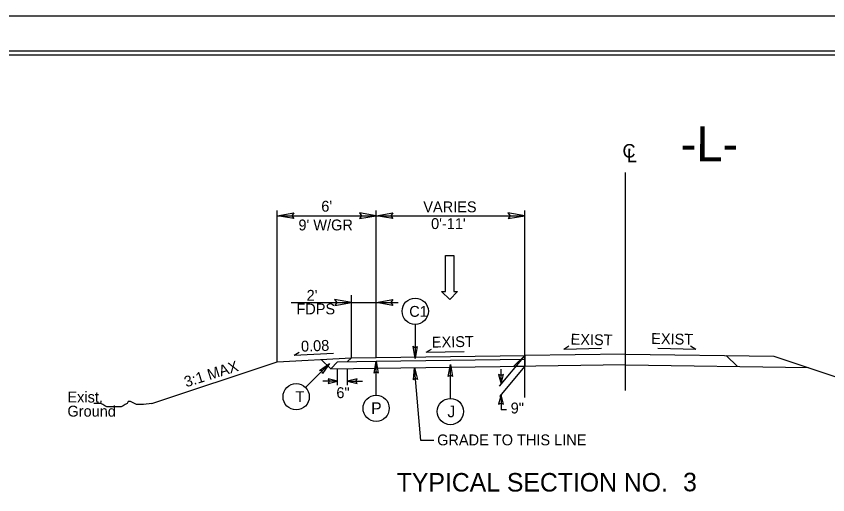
# Model space of a CAD drawing. Extents: x 1497225 to 1499181, y 579958 to 582278.
# Drawn here: x 1497748 to 1498271, y 580750 to 581058 of the extents above; entities that cross this region are included whole.
import ezdxf

# ---------------------------------------------------------------- set-up
doc = ezdxf.new("R2010")
doc.units = 0
for name, color, linetype in [('Old_Level_1', 7, 'Continuous'), ('Old_Level_11', 7, 'Continuous'), ('Old_Level_4', 7, 'Continuous'), ('Sheet Cutting Line CELL', 7, 'Continuous'), ('Sheet Plot Border Inside CELL', 7, 'Continuous'), ('Sheet Plot Border Outside CELL', 7, 'Continuous'), ('Sheet Typical CELL', 7, 'Continuous'), ('Typical ID Circle CELL', 7, 'Continuous'), ('Typical Terminator CELL', 7, 'Continuous'), ('Typical Text ID Circle CELL', 7, 'Continuous'), ('Typical Text Label CELL', 7, 'Continuous')]:
    doc.layers.add(name, color=color, linetype=linetype)

# ---------------------------------------------------------------- blocks, each defined once
blk = doc.blocks.new('TERMINATOR')
at = {"layer": 'Typical Terminator CELL'}
blk.add_lwpolyline([(-0.469, 0.081), (0, 0), (-0.471, -0.083), (-0.411, 0)], close=True, dxfattribs=at)

msp = doc.modelspace()

# ---------------------------------------------------------------- linework, layer by layer
at = {"layer": 'Old_Level_1'}
for p, q in [((1498140.92, 580816.81), (1498140.92, 580957.33)), ((1497916.36, 580835.27), (1497916.36, 580932.92)), ((1497916.36, 580929.48), (1497980.21, 580929.48)), ((1497980.21, 580838.15), (1497980.21, 580932.92)), ((1497980.21, 580929.48), (1498075.97, 580929.48)), ((1498075.97, 580812.23), (1498075.97, 580932.92)), ((1497964.25, 580837.93), (1497964.25, 580878.15)), ((1497925.39, 580873.5), (1497994.41, 580873.5)), ((1497964.25, 580873.5), (1497980.21, 580873.5)), ((1498101.09, 580843.51), (1498104.47, 580845.55)), ((1498186.23, 580843.32), (1498182.86, 580845.36)), ((1497927.3, 580839.48), (1497930.67, 580841.52)), ((1497927.3, 580839.48), (1497952.81, 580840.85)), ((1497980.21, 580838.15), (1498075.97, 580839.42)), ((1498012.55, 580841.42), (1498015.92, 580843.46)), ((1498012.55, 580841.42), (1498037.01, 580841.91)), ((1498075.97, 580839.42), (1498059.49, 580819.59)), ((1498075.97, 580839.42), (1498068.81, 580832.26)), ((1498140.92, 580840.3), (1498075.97, 580839.42)), ((1498075.97, 580839.42), (1498075.97, 580832.5)), ((1498101.09, 580843.51), (1498125.56, 580844)), ((1498140.92, 580840.3), (1498236.52, 580839.01)), ((1498186.23, 580843.32), (1498161.77, 580843.81)), ((1498205.87, 580839.42), (1498213.04, 580832.26)), ((1498236.52, 580839.01), (1498329.02, 580808.17)), ((1497835.57, 580808.34), (1497916.36, 580835.27)), ((1497916.36, 580835.27), (1497964.25, 580837.93)), ((1497944.89, 580836.85), (1497950.92, 580830.83)), ((1497950.92, 580830.83), (1497955.41, 580835.32)), ((1497955.41, 580835.32), (1497980.21, 580835.66)), ((1497961.73, 580835.41), (1497964.25, 580837.93)), ((1497964.25, 580837.93), (1497980.21, 580838.15)), ((1497980.21, 580835.66), (1498075.97, 580836.94)), ((1497950.92, 580830.83), (1497980.21, 580831.23)), ((1497955.41, 580820.22), (1497955.41, 580830.89)), ((1497961.73, 580820.22), (1497961.73, 580830.98)), ((1497980.21, 580831.23), (1498075.97, 580832.5)), ((1498008.96, 580784.68), (1498004.86, 580831.56)), ((1498075.97, 580832.5), (1498059.64, 580812.86)), ((1498060.69, 580821.04), (1498060.69, 580830.67)), ((1498140.92, 580833.44), (1498068.81, 580832.39)), ((1498140.92, 580833.31), (1498258.77, 580831.59)), ((1497955.41, 580822.79), (1497945.79, 580822.79)), ((1497961.73, 580822.79), (1497971.36, 580822.79)), ((1498060.69, 580814.13), (1498060.69, 580804.46)), ((1498064.24, 580804.46), (1498060.69, 580804.46)), ((1498017.35, 580784.68), (1498008.96, 580784.68))]:
    msp.add_line(p, q, dxfattribs=at)
msp.add_lwpolyline([(1497835.57, 580808.34), (1497830.33, 580807.69), (1497829.02, 580807.69), (1497827.05, 580807.69), (1497825.74, 580807.69), (1497824.42, 580808.34), (1497823.11, 580809), (1497821.8, 580809.66), (1497820.49, 580809.66), (1497819.83, 580808.34), (1497818.52, 580807.69), (1497817.21, 580807.03), (1497815.9, 580806.38), (1497814.59, 580806.38), (1497813.28, 580806.38), (1497811.97, 580806.38), (1497810.65, 580806.38), (1497809.34, 580806.38), (1497808.03, 580806.38), (1497806.72, 580806.38), (1497805.41, 580807.03), (1497804.1, 580807.69), (1497802.79, 580808.34), (1497800.82, 580808.34), (1497799.51, 580808.34), (1497798.2, 580808.34)], dxfattribs=at)
at = {"layer": 'Old_Level_11'}
for points in [[(1497927.08, 580927.6), (1497916.36, 580929.48), (1497927.17, 580931.37), (1497925.79, 580929.48)], [(1497969.48, 580927.6), (1497980.21, 580929.48), (1497969.4, 580931.37), (1497970.77, 580929.48)], [(1497990.93, 580927.6), (1497980.21, 580929.48), (1497991.02, 580931.37), (1497989.64, 580929.48)], [(1498065.24, 580927.6), (1498075.97, 580929.48), (1498065.16, 580931.37), (1498066.53, 580929.48)], [(1497953.52, 580871.61), (1497964.25, 580873.5), (1497953.44, 580875.38), (1497954.81, 580873.5)], [(1497990.93, 580871.61), (1497980.21, 580873.5), (1497991.02, 580875.38), (1497989.64, 580873.5)]]:
    msp.add_lwpolyline(points, close=True, dxfattribs=at)
at = {"layer": 'Old_Level_4'}
for p, q in [((1498024.83, 580880.65), (1498024.83, 580903.75)), ((1498024.83, 580903.75), (1498030.28, 580903.75)), ((1498030.28, 580903.75), (1498030.28, 580880.65)), ((1498027.64, 580875.45), (1498022.36, 580880.65)), ((1498022.36, 580880.65), (1498024.83, 580880.65)), ((1498032.75, 580880.65), (1498027.64, 580875.45)), ((1498030.28, 580880.65), (1498032.75, 580880.65))]:
    msp.add_line(p, q, dxfattribs=at)
msp.add_lwpolyline([(1498004.21, 580823.74), (1498004.86, 580831.56), (1498006.91, 580823.93), (1498005.45, 580824.79)], close=True, dxfattribs=at)
at = {"layer": 'Sheet Cutting Line CELL'}
msp.add_line((1498909.23, 581058.02), (1497225.23, 581058.02), dxfattribs=at)
at = {"layer": 'Sheet Plot Border Inside CELL'}
msp.add_lwpolyline([(1498904.73, 581035.57), (1497238.23, 581035.57), (1497238.23, 579980.47), (1498904.73, 579980.47)], close=True, dxfattribs=at)
at = {"layer": 'Sheet Plot Border Outside CELL'}
msp.add_lwpolyline([(1498909.23, 581058.02), (1497225.23, 581058.02), (1497225.23, 579958.02), (1498909.23, 579958.02)], close=True, dxfattribs=at)
at = {"layer": 'Sheet Typical CELL'}
msp.add_lwpolyline([(1498892.23, 581033.02), (1497392.23, 581033.02), (1497392.23, 579983.02), (1498892.23, 579983.02)], close=True, dxfattribs=at)
at = {"layer": 'Typical ID Circle CELL'}
for p, q in [((1498005.4, 580859.41), (1498005.4, 580837.54)), ((1497934.67, 580818.79), (1497950.14, 580834.25)), ((1497980.21, 580813.79), (1497980.21, 580835.66)), ((1498028.07, 580811.71), (1498028.07, 580833.58))]:
    msp.add_line(p, q, dxfattribs=at)
for centre in [(1498005.4, 580867.87), (1497928.69, 580812.8), (1497980.21, 580805.33), (1498028.07, 580803.25)]:
    msp.add_circle(centre, 8.46, dxfattribs=at)
at = {"layer": 'Typical Terminator CELL'}
for points in [[(1498006.73, 580845.27), (1498005.4, 580837.54), (1498004.03, 580845.32), (1498005.4, 580844.33)], [(1497943.73, 580829.73), (1497950.14, 580834.25), (1497945.61, 580827.78), (1497945.34, 580829.45)], [(1497978.88, 580827.93), (1497980.21, 580835.66), (1497981.58, 580827.89), (1497980.21, 580828.88)], [(1498026.74, 580825.85), (1498028.07, 580833.58), (1498029.44, 580825.81), (1498028.07, 580826.8)]]:
    msp.add_lwpolyline(points, close=True, dxfattribs=at)

# ---------------------------------------------------------------- block references
at = {"layer": 'Old_Level_4', "xscale": 13.123011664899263, "yscale": -18.835616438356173}
for p, rotation in [((1497955.41, 580822.79), 3.946795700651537e-12), ((1497961.73, 580822.79), -179.99999999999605), ((1498060.69, 580821.04), -89.99999999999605), ((1498060.69, 580814.13), 90.00000000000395)]:
    msp.add_blockref('TERMINATOR', p, dxfattribs=dict(at, rotation=rotation))

# ---------------------------------------------------------------- texts
at = {"layer": 'Old_Level_1'}
for s, height, rotation, p in [('-L-', 22.68, 359.9492, (1498176.45, 580964.49)), ('L', 8.73, 359.9469, (1498141.88, 580963.93)), ('0.08', 7, 2.0686, (1497931.91, 580841.82)), ('EXIST', 7, 1.1457, (1498016.17, 580844.45)), ('EXIST', 7, 358.8106, (1498105.48, 580846.4)), ('EXIST', 7, 358.8106, (1498157.41, 580846.83)), ('3:1 MAX', 7, 17.4404, (1497857.79, 580818.81)), ('Exist.', 7, 359.9492, (1497781.25, 580809.1)), ('Ground', 7, 359.9492, (1497781.25, 580800))]:
    msp.add_text(s, height=height, rotation=rotation, dxfattribs=at).set_placement(p)
for s, height, p in [('C', 8.73, (1498138.98, 580966.91)), ("6'", 7, (1497944.87, 580932.08)), ('VARIES', 7, (1498010.61, 580931.68)), ("0'-11'", 7, (1498015.63, 580920.87)), ("9' W/GR", 7, (1497930.13, 580919.99)), ("2'", 7, (1497935.41, 580874.64)), ('FDPS', 7, (1497928.83, 580865.89)), ('GRADE TO THIS LINE', 7, (1498019.54, 580781.47))]:
    msp.add_text(s, height=height, dxfattribs=at).set_placement(p)
at = {"layer": 'Old_Level_4'}
for s, p in [('6"', (1497954.59, 580811.9)), ('9"', (1498066.93, 580802.03))]:
    msp.add_text(s, height=7, rotation=360, dxfattribs=at).set_placement(p)
at = {"layer": 'Typical Text ID Circle CELL'}
for s, height, p in [('C1', 7, (1498001.54, 580864.3)), ('T', 7, (1497928.23, 580809.32)), ('P', 7.58, (1497976.98, 580801.64)), ('J', 7.58, (1498026.16, 580799.56))]:
    msp.add_text(s, height=height, dxfattribs=at).set_placement(p)
at = {"layer": 'Typical Text Label CELL'}
for s, height, p in [('TYPICAL SECTION NO.  ', 11.9356, (1497993.52, 580751.7)), ('3', 11.94, (1498178.04, 580751.86))]:
    msp.add_text(s, height=height, dxfattribs=at).set_placement(p)

doc.saveas('drawing.dxf')
